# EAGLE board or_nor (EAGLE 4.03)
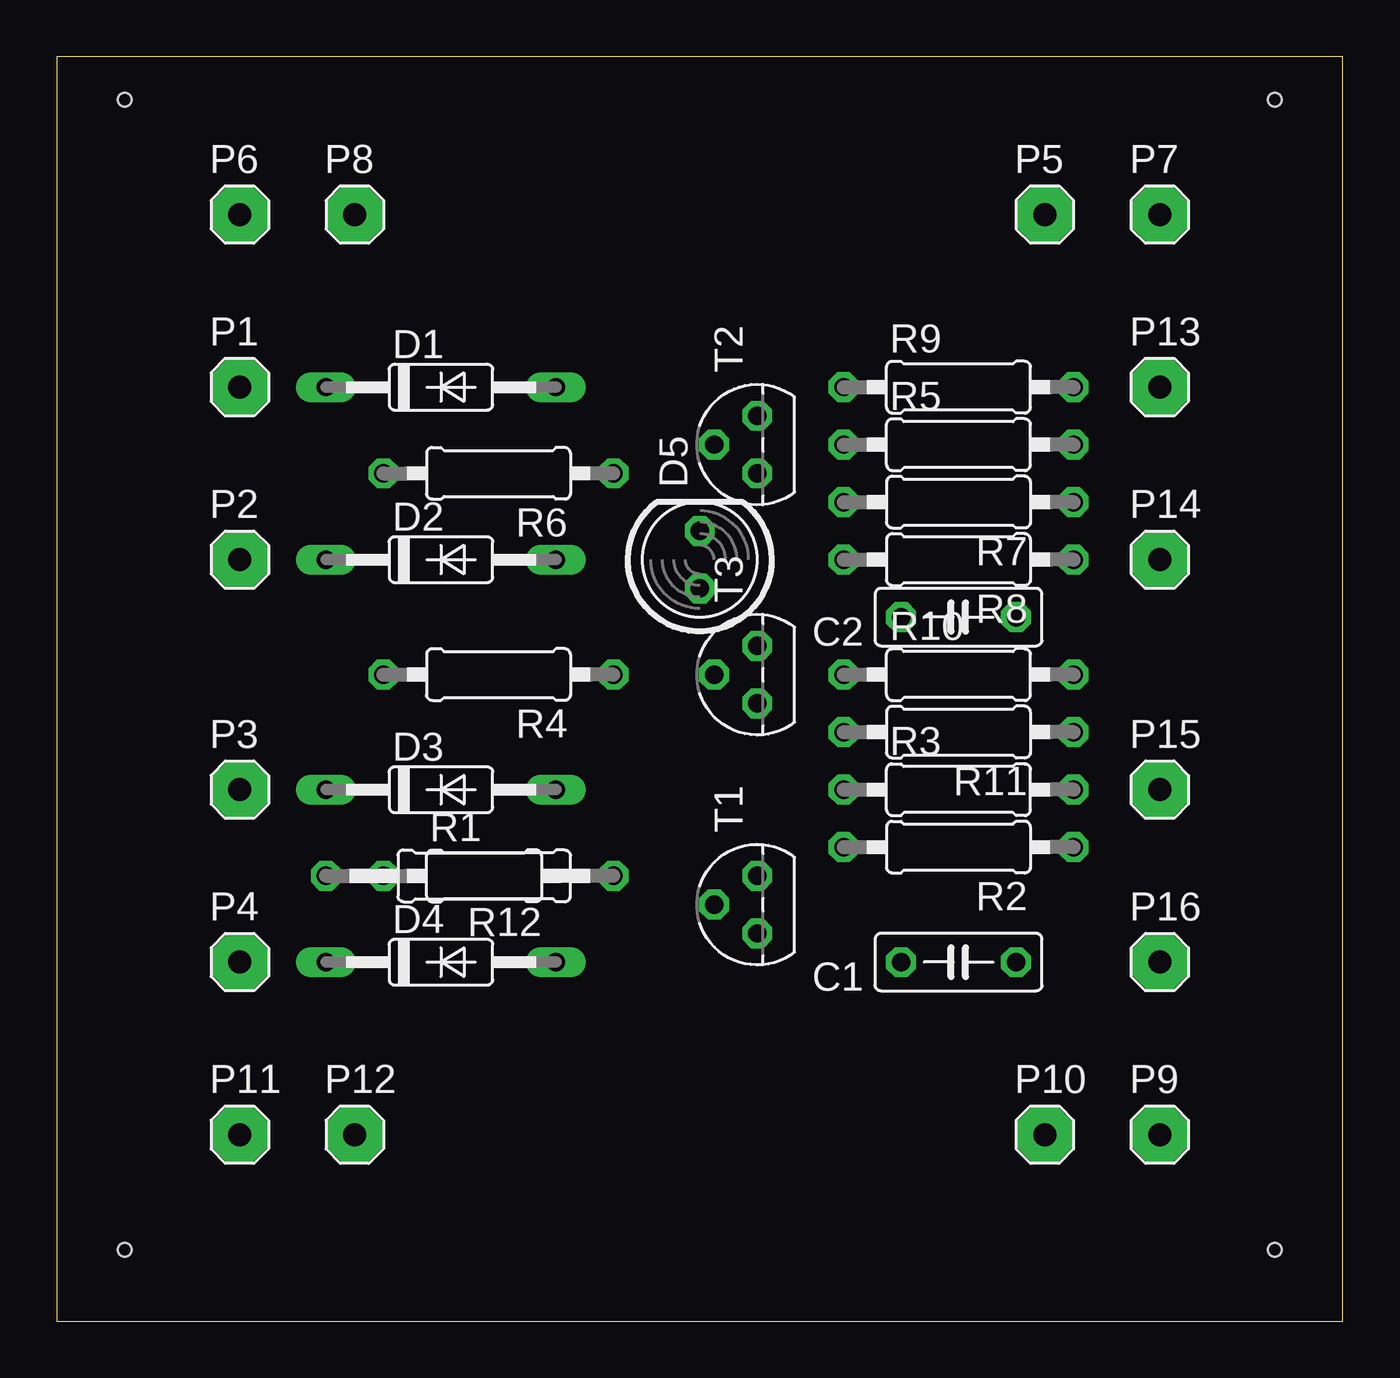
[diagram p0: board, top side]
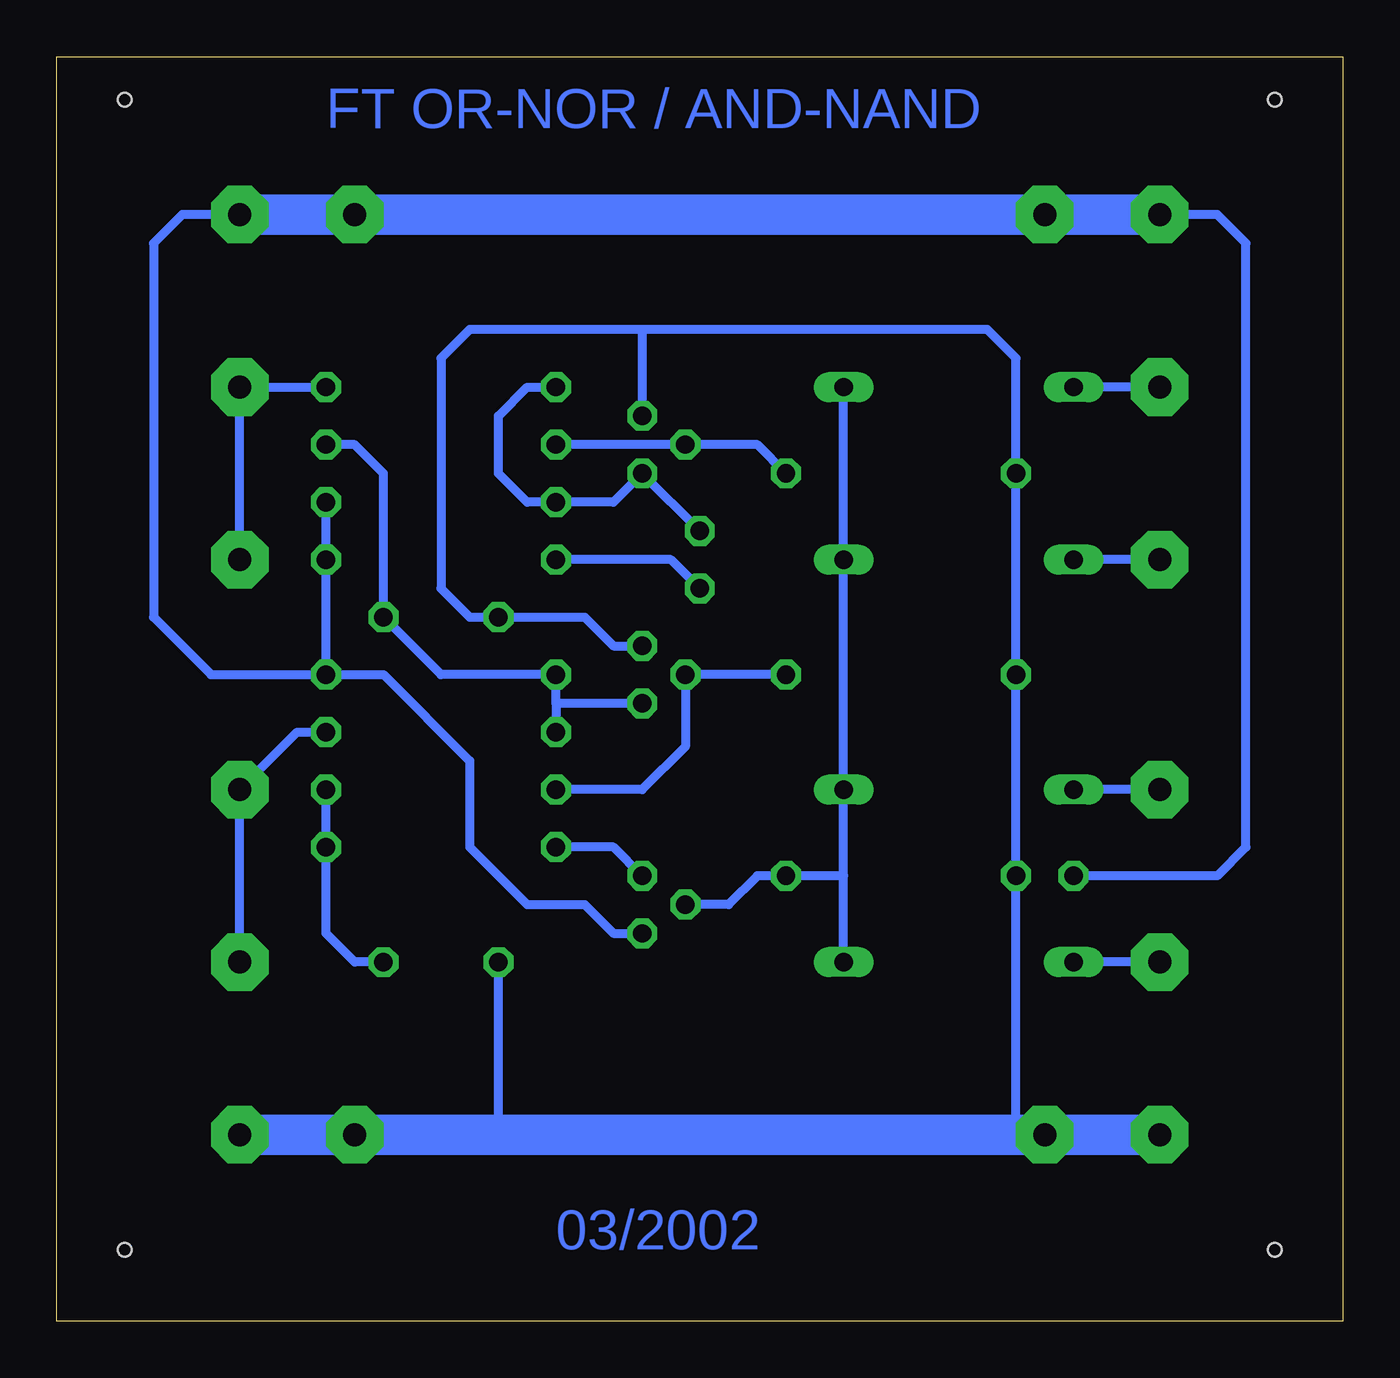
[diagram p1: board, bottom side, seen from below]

Size 56.82 x 55.87 mm. Coordinates in mm from the lower left corner, seen from the top.
Outline: 0,0 56.82,0 56.82,55.87 0,55.87 0,0
Copper layers used: Bottom
Holes 0.61 mm at 3.01,3.17 3.01,53.97 53.81,53.97 53.81,3.17

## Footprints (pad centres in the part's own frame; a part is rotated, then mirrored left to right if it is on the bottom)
C050-025X075 = drill 0.813 octagon: 1 -2.54,0; 2 2.54,0
DO35-10 = drill 0.813 long: A 5.08,0; C -5.08,0
LED5MM = drill 0.813 octagon: A -1.27,0; K 1.27,0
1X01 = drill 1.016 pad 2.54 octagon: 1 0,0
0207/10 = drill 0.813 octagon: 1 -5.08,0; 2 5.08,0
0207/12 = drill 0.813 octagon: 1 -6.35,0; 2 6.35,0
TO92 = drill 0.813 octagon: 1 1.27,0; 2 0,1.905; 3 -1.27,0

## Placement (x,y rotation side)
C1  22n  [C050-025X075]  39.84,15.87 180 top
C2  22n  [C050-025X075]  39.84,31.11 180 top
D1  1N4148  [DO35-10]  16.98,41.27 0 top
D2  1N4148  [DO35-10]  16.98,33.65 0 top
D3  1N4148  [DO35-10]  16.98,23.49 0 top
D4  1N4148  [DO35-10]  16.98,15.87 0 top
D5  LED5MM  [LED5MM]  28.41,33.65 90 top
P1  A  [1X01]  8.09,41.27 0 top
P2  B  [1X01]  8.09,33.65 0 top
P3  C  [1X01]  8.09,23.49 0 top
P4  C  [1X01]  8.09,15.87 0 top
P5  +9V  [1X01]  43.65,48.89 0 top
P6  +9V  [1X01]  8.09,48.89 0 top
P7  +9V  [1X01]  48.73,48.89 0 top
P8  +9V  [1X01]  13.17,48.89 0 top
P9  GND  [1X01]  48.73,8.25 0 top
P10  GND  [1X01]  43.65,8.25 0 top
P11  GND  [1X01]  8.09,8.25 0 top
P12  GND  [1X01]  13.17,8.25 0 top
P13  OR  [1X01]  48.73,41.27 0 top
P14  OR  [1X01]  48.73,33.65 0 top
P15  NOR  [1X01]  48.73,23.49 0 top
P16  NOR  [1X01]  48.73,15.87 0 top
R1  10K  [0207/10]  19.52,19.68 0 top
R2  1K5  [0207/10]  39.84,20.95 180 top
R3  330R  [0207/10]  39.84,23.49 0 top
R4  33K  [0207/10]  19.52,28.57 180 top
R5  5K6  [0207/10]  39.84,38.73 0 top
R6  1K  [0207/10]  19.52,37.46 180 top
R7  1K  [0207/10]  39.84,36.19 180 top
R8  220R  [0207/10]  39.84,33.65 180 top
R9  82R  [0207/10]  39.84,41.27 0 top
R10  560R  [0207/10]  39.84,28.57 0 top
R11  82R  [0207/10]  39.84,26.03 180 top
R12  [0207/12]  18.25,19.68 180 top
T1  BC238  [TO92]  30.95,18.41 90 top
T2  BC238  [TO92]  30.95,38.73 90 top
T3  BC238  [TO92]  30.95,28.57 90 top

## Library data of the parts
C1 C2 R1-R12 = rcl
D1-D4 = diode
D5 = led
P1-P16 = pinhead
T1-T3 = transistor-npn

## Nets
N$1: C1.2 C2.2 P9.1 P10.1 P11.1 P12.1 R1.1 R4.2 R6.2 T2.1 T3.1
N$3: P5.1 P6.1 P7.1 P8.1 R7.1 R8.1 R10.2 R12.2 T1.3
N$4: D5.A R8.2
N$6: D5.K R7.2 R9.1 T2.3
N$11: R5.1 R6.1 T2.2
N$12: C2.1 R5.2 R10.1 R11.2 T3.3
N$16: R3.1 R4.1 T3.2
N$20: D1.A D2.A D3.A D4.A R1.2 R12.1 T1.2
N$25: D1.C P1.1
N$26: D2.C P2.1
N$27: D3.C P3.1
N$28: D4.C P4.1
N$30: R2.2 T1.1
N$31: C1.1 R2.1 R3.2
N$34: P13.1 P14.1 R9.2
N$35: P15.1 P16.1 R11.1

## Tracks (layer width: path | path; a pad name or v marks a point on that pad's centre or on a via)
N$1
  Bottom 0.406: 37.3,8.25 C1.2 | T3.1 32.22,29.84 33.49,31.11 C2.2 38.57,31.11 39.84,32.38 39.84,42.54 38.57,43.81 30.95,43.81 | 30.95,43.81 15.71,43.81 14.44,42.54 R6.2 R4.2 R1.1 14.44,8.25 | 30.95,43.81 T2.1
  Bottom 1.778: P11.1 P12.1 14.44,8.25 37.3,8.25 P10.1 P9.1
N$3
  Bottom 0.406: R10.2 50,28.57 52.54,31.11 52.54,47.62 51.27,48.89 P7.1 | R7.1 R8.1 R10.2 | P6.1 5.55,48.89 4.28,47.62 4.28,20.95 5.55,19.68 R12.2 | T1.3 32.22,17.14 33.49,18.41 36.03,18.41 38.57,20.95 38.57,24.76 42.38,28.57 R10.2
  Bottom 1.778: P6.1 P8.1 P5.1 P7.1
N$4
  Bottom 0.406: R8.2 29.68,33.65 D5.A
N$6
  Bottom 0.406: R9.1 36.03,41.27 37.3,40 37.3,37.46 36.03,36.19 R7.2 32.22,36.19 T2.3 D5.K
N$11
  Bottom 0.406: R6.1 25.87,38.73 T2.2 R5.1
N$12
  Bottom 0.406: T3.3 34.76,27.3 | 34.76,27.3 R11.2 | R5.2 43.65,38.73 42.38,37.46 C2.1 39.84,28.57 R10.1 34.76,27.3
N$16
  Bottom 0.406: R3.1 30.95,23.49 29.04,25.39 T3.2 R4.1
N$20
  Bottom 0.406: D1.A D2.A D3.A 22.06,19.68 | D4.A 22.06,19.68 | 22.06,19.68 R1.2 25.87,19.68 27.14,18.41 T1.2
N$25
  Bottom 0.406: P1.1 D1.C
N$26
  Bottom 0.406: P2.1 D2.C
N$27
  Bottom 0.406: P3.1 D3.C
N$28
  Bottom 0.406: P4.1 D4.C
N$30
  Bottom 0.406: R2.2 32.22,20.95 T1.1
N$31
  Bottom 0.406: C1.1 43.65,15.87 44.92,17.14 R2.1 R3.2
N$34
  Bottom 0.406: P14.1 P13.1 R9.2
N$35
  Bottom 0.406: P16.1 P15.1 46.19,26.03 R11.1

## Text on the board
Bottom: FT OR-NOR / AND-NAND | 03/2002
